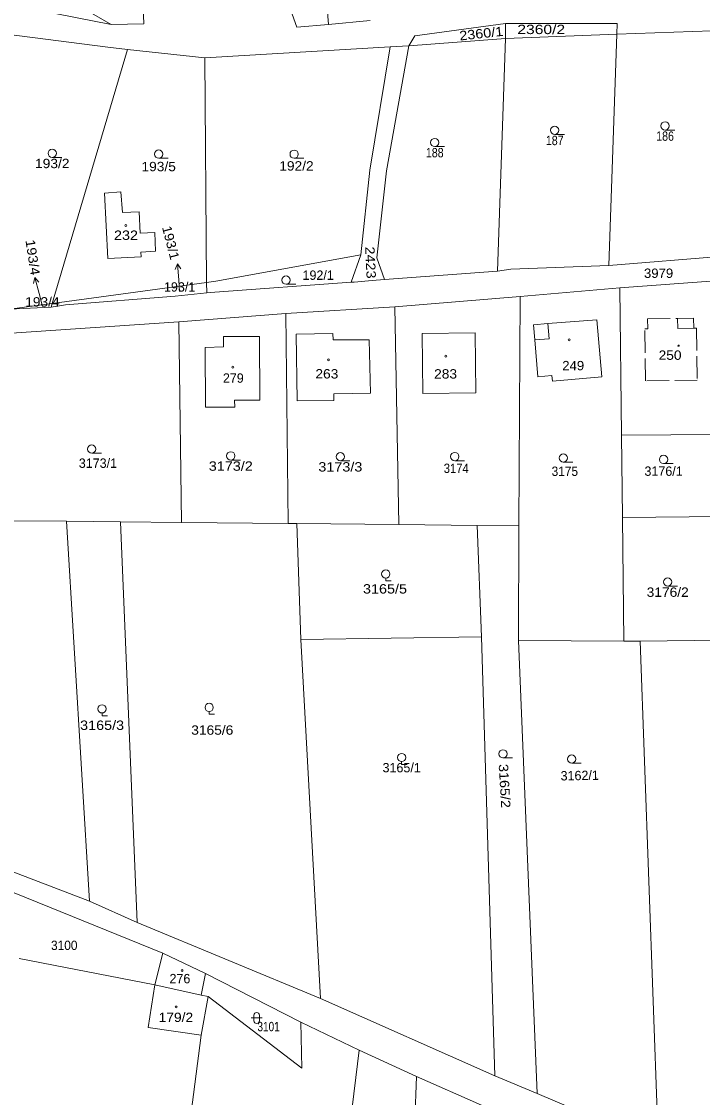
# Model space of a CAD drawing. Extents: x -590528 to -586543, y -1119609 to -1116685.
# Drawn here: x -588918.3 to -588794.5, y -1118317.2 to -1118121.8 of the extents above; entities that cross this region are included whole.
import ezdxf
from ezdxf.enums import TextEntityAlignment as Align

# ---------------------------------------------------------------- set-up
doc = ezdxf.new("R2010")
doc.units = 0
doc.header["$LTSCALE"] = 0.68
doc.linetypes.add('LONG_DASHED', pattern=[7.5, 6, -1.5])
for name, color, linetype, lineweight in [('1', 7, 'Continuous', 13), ('2', 7, 'LONG_DASHED', 13), ('3', 7, 'Continuous', 13), ('6', 7, 'Continuous', 13)]:
    doc.layers.add(name, color=color, linetype=linetype, lineweight=lineweight)

msp = doc.modelspace()

# ---------------------------------------------------------------- linework, layer by layer
at = {"layer": '1'}
for p, q in [((-588921.38, -1118118.49), (-588901.98, -1118122.35)), ((-588896.04, -1118122.23), (-588896.14, -1118119.24)), ((-588862.48, -1118122.31), (-588854.92, -1118121.59)), ((-588896.04, -1118122.23), (-588901.98, -1118122.35)), ((-588902.6, -1118126.42), (-588920.96, -1118124.06)), ((-588830.31, -1118124.87), (-588810.07, -1118124.07)), ((-588810.07, -1118124.07), (-588811.54, -1118166.12)), ((-588851.29, -1118126.41), (-588854.96, -1118148.79)), ((-588847.89, -1118126.18), (-588851.91, -1118148.91)), ((-588884.62, -1118169.19), (-588884.95, -1118128.37)), ((-588854.96, -1118148.79), (-588856.61, -1118164.19)), ((-588851.91, -1118148.91), (-588853.69, -1118164.7)), ((-588903.19, -1118152.99), (-588900.21, -1118152.75)), ((-588899.91, -1118156.48), (-588900.21, -1118152.75)), ((-588899.91, -1118156.48), (-588896.85, -1118156.35)), ((-588896.69, -1118160.23), (-588896.85, -1118156.35)), ((-588894.05, -1118160.12), (-588896.69, -1118160.23)), ((-588893.91, -1118163.53), (-588894.05, -1118160.12)), ((-588856.61, -1118164.19), (-588858.33, -1118169.16)), ((-588853.69, -1118164.7), (-588852.27, -1118168.64)), ((-588790.67, -1118164.38), (-588811.54, -1118166.12)), ((-588811.54, -1118166.12), (-588829.34, -1118166.77)), ((-588854.57, -1118168.83), (-588852.27, -1118168.64)), ((-588852.27, -1118168.64), (-588831.79, -1118167.15)), ((-588831.79, -1118167.15), (-588829.34, -1118166.77)), ((-588884.6, -1118171.06), (-588884.62, -1118169.19)), ((-588883.12, -1118170.94), (-588858.33, -1118169.16)), ((-588858.33, -1118169.16), (-588857.79, -1118169.12)), ((-588857.79, -1118169.12), (-588854.57, -1118168.83)), ((-588827.67, -1118171.72), (-588809.52, -1118170.19)), ((-588809.23, -1118196.92), (-588809.52, -1118170.19)), ((-588910.29, -1118173.25), (-588890.36, -1118171.66)), ((-588890.36, -1118171.66), (-588884.6, -1118171.06)), ((-588884.6, -1118171.06), (-588883.12, -1118170.94)), ((-588850.41, -1118173.6), (-588827.67, -1118171.72)), ((-588870.25, -1118174.81), (-588850.41, -1118173.6)), ((-588849.68, -1118213.18), (-588850.41, -1118173.6)), ((-588889.64, -1118176.31), (-588920.1, -1118178.41)), ((-588889.64, -1118176.31), (-588870.25, -1118174.81)), ((-588889.19, -1118212.78), (-588889.64, -1118176.31)), ((-588869.8, -1118212.97), (-588870.25, -1118174.81)), ((-588854.85, -1118189.3), (-588855.08, -1118179.59)), ((-588845.36, -1118189.35), (-588845.46, -1118178.46)), ((-588884.88, -1118181), (-588881.54, -1118180.86)), ((-588884.8, -1118191.86), (-588884.88, -1118181)), ((-588879.52, -1118191.82), (-588884.8, -1118191.86)), ((-588791.29, -1118196.8), (-588809.23, -1118196.92)), ((-588809.23, -1118196.92), (-588809.06, -1118211.89)), ((-588910.11, -1118212.57), (-588905.88, -1118281.56)), ((-588897.24, -1118285.43), (-588900.28, -1118212.67)), ((-588900.28, -1118212.67), (-588889.19, -1118212.78)), ((-588889.19, -1118212.78), (-588869.8, -1118212.97)), ((-588869.8, -1118212.97), (-588868.22, -1118212.99)), ((-588868.22, -1118212.99), (-588867.52, -1118234.07)), ((-588835.44, -1118213.32), (-588834.7, -1118233.55)), ((-588835.44, -1118213.32), (-588827.88, -1118213.39)), ((-588790.86, -1118211.7), (-588809.06, -1118211.89)), ((-588809.06, -1118211.89), (-588808.81, -1118234.37)), ((-588867.52, -1118234.07), (-588834.7, -1118233.55)), ((-588867.52, -1118234.07), (-588863.93, -1118299.24)), ((-588834.7, -1118233.55), (-588832.25, -1118313.27)), ((-588827.98, -1118234.2), (-588808.81, -1118234.37)), ((-588827.98, -1118234.2), (-588824.58, -1118316.52)), ((-588805.82, -1118234.34), (-588802.56, -1118325.8)), ((-588905.88, -1118281.56), (-588948.76, -1118265.18)), ((-588921.53, -1118279.24), (-588892.58, -1118291.03)), ((-588905.88, -1118281.56), (-588897.24, -1118285.43)), ((-588897.24, -1118285.43), (-588863.93, -1118299.24)), ((-588892.58, -1118291.03), (-588884.8, -1118294.68)), ((-588894, -1118296.78), (-588918.7, -1118292.01)), ((-588884.8, -1118294.68), (-588885.6, -1118298.63)), ((-588885.6, -1118298.63), (-588894, -1118296.78)), ((-588884.32, -1118298.91), (-588885.6, -1118298.63)), ((-588884.32, -1118298.91), (-588867.3, -1118311.88)), ((-588863.93, -1118299.24), (-588832.25, -1118313.27)), ((-588885.59, -1118305.94), (-588895.27, -1118304.49)), ((-588867.3, -1118311.88), (-588867.49, -1118303.56)), ((-588856.9, -1118308.63), (-588863.85, -1118365.56)), ((-588824.58, -1118316.52), (-588832.25, -1118313.27)), ((-588848.61, -1118373.89), (-588846.49, -1118313.43)), ((-588802.56, -1118325.8), (-588824.58, -1118316.52))]:
    msp.add_line(p, q, dxfattribs=at)
for points in [[(-588863.89, -1118102.64), (-588862.81, -1118117.75), (-588862.48, -1118122.31), (-588868.2, -1118122.84), (-588869.94, -1118118.08)], [(-588918.11, -1118109.25), (-588909.85, -1118117.75), (-588901.98, -1118122.35)], [(-588847.89, -1118126.18), (-588846.78, -1118124.38), (-588830.31, -1118122.15), (-588830.31, -1118124.87)], [(-588830.31, -1118122.15), (-588810.04, -1118122.15), (-588810.07, -1118124.07)], [(-588810.07, -1118124.07), (-588789.39, -1118123.38), (-588790.67, -1118164.38)], [(-588884.95, -1118128.37), (-588851.29, -1118126.41), (-588847.89, -1118126.18), (-588830.31, -1118124.87), (-588831.79, -1118167.15)], [(-588898.98, -1118126.89), (-588912.66, -1118173), (-588912.87, -1118173.7)], [(-588884.95, -1118128.37), (-588898.98, -1118126.89), (-588902.6, -1118126.42)], [(-588903.19, -1118152.99), (-588902.55, -1118164.84), (-588896.51, -1118164.53)], [(-588893.91, -1118163.53), (-588896.55, -1118163.67), (-588896.51, -1118164.53)], [(-588884.62, -1118169.19), (-588882.94, -1118168.96), (-588856.61, -1118164.19)], [(-588920.43, -1118174.06), (-588912.66, -1118173), (-588884.62, -1118169.19)], [(-588809.52, -1118170.19), (-588792.21, -1118168.92), (-588791.29, -1118196.8)], [(-588827.67, -1118171.72), (-588827.88, -1118213.39), (-588827.98, -1118234.2)], [(-588920.43, -1118174.06), (-588912.87, -1118173.7), (-588910.29, -1118173.25)], [(-588825.2, -1118176.88), (-588822.6, -1118176.67), (-588813.69, -1118175.95)], [(-588821.8, -1118187.11), (-588812.81, -1118186.35), (-588813.69, -1118175.95)], [(-588845.36, -1118189.35), (-588835.69, -1118189.21), (-588835.8, -1118178.35), (-588845.46, -1118178.46)], [(-588825.2, -1118176.88), (-588824.99, -1118179.63), (-588824.45, -1118186.32), (-588821.89, -1118186.11), (-588821.8, -1118187.11)], [(-588874.99, -1118178.99), (-588881.53, -1118178.99), (-588881.54, -1118180.86)], [(-588874.99, -1118178.99), (-588874.94, -1118190.54), (-588879.53, -1118190.57), (-588879.52, -1118191.82)], [(-588855.08, -1118179.59), (-588861.65, -1118179.61), (-588861.67, -1118178.46), (-588868.37, -1118178.55), (-588868.18, -1118190.71)], [(-588868.18, -1118190.71), (-588861.48, -1118190.61), (-588861.5, -1118189.41), (-588854.85, -1118189.3)], [(-588919.7, -1118212.47), (-588910.11, -1118212.57), (-588900.28, -1118212.67)], [(-588868.22, -1118212.99), (-588849.68, -1118213.18), (-588835.44, -1118213.32)], [(-588808.81, -1118234.37), (-588805.82, -1118234.34), (-588791.09, -1118234.19), (-588773.86, -1118234.48), (-588772.6, -1118234.5)], [(-588892.58, -1118291.03), (-588894, -1118296.78), (-588895.27, -1118304.49)], [(-588856.9, -1118308.63), (-588867.49, -1118303.56), (-588884.8, -1118294.68)], [(-588884.32, -1118298.91), (-588885.59, -1118305.94), (-588889.71, -1118337.74)], [(-588834.65, -1118318.61), (-588846.49, -1118313.43), (-588856.9, -1118308.63)]]:
    msp.add_lwpolyline(points, dxfattribs=at)
at = {"layer": '2'}
for p, q in [((-588804.46, -1118177.62), (-588804.49, -1118175.8)), ((-588799.05, -1118175.72), (-588799.02, -1118177.54)), ((-588804.46, -1118177.62), (-588805.01, -1118177.63)), ((-588799.02, -1118177.54), (-588796.11, -1118177.49))]:
    msp.add_line(p, q, dxfattribs=at)
for points in [[(-588804.49, -1118175.8), (-588799.05, -1118175.72), (-588796.14, -1118175.67)], [(-588796.14, -1118175.67), (-588796.11, -1118177.49), (-588795.61, -1118177.48)], [(-588824.99, -1118179.63), (-588822.39, -1118179.41), (-588822.6, -1118176.67)], [(-588795.61, -1118177.48), (-588795.46, -1118186.93), (-588804.85, -1118187.08), (-588805.01, -1118177.63)]]:
    msp.add_lwpolyline(points, dxfattribs=at)
at = {"layer": '3'}
for p, q in [((-588889.886, -1118165.778), (-588889.67, -1118168.77)), ((-588915.821, -1118168.286), (-588915.07, -1118171.19)), ((-588889.52, -1118170.85), (-588889.67, -1118168.77)), ((-588914.46, -1118173.56), (-588915.07, -1118171.19))]:
    msp.add_line(p, q, dxfattribs=at)
for points in [[(-588890.312, -1118166.811), (-588889.886, -1118165.778), (-588889.314, -1118166.74)], [(-588916.054, -1118169.378), (-588915.821, -1118168.286), (-588915.085, -1118169.129)]]:
    msp.add_lwpolyline(points, dxfattribs=at)
at = {"layer": '6'}
for p, q in [((-588821.37, -1118142.29), (-588819.62, -1118142.29)), ((-588801.32, -1118141.5), (-588799.57, -1118141.5)), ((-588843.17, -1118144.51), (-588841.42, -1118144.51)), ((-588912.67, -1118146.47), (-588910.92, -1118146.47)), ((-588893.33, -1118146.62), (-588891.58, -1118146.62)), ((-588868.72, -1118146.63), (-588866.97, -1118146.63)), ((-588870.19, -1118169.51), (-588868.44, -1118169.51)), ((-588905.5, -1118200.2), (-588903.75, -1118200.2)), ((-588880.23, -1118201.44), (-588878.48, -1118201.44)), ((-588860.32, -1118201.58), (-588858.57, -1118201.58)), ((-588839.53, -1118201.56), (-588837.78, -1118201.56)), ((-588819.81, -1118201.82), (-588818.06, -1118201.82)), ((-588801.59, -1118202.08), (-588799.84, -1118202.08)), ((-588800.84, -1118224.34), (-588799.09, -1118224.34)), ((-588830.77, -1118255.56), (-588829.02, -1118255.56)), ((-588818.29, -1118256.51), (-588816.54, -1118256.51)), ((-588876.53, -1118302.79), (-588874.53, -1118302.79)), ((-588876.03, -1118303.29), (-588876.03, -1118302.29)), ((-588875.03, -1118303.29), (-588875.03, -1118302.29))]:
    msp.add_line(p, q, dxfattribs=at)
for points in [[(-588852.07, -1118222.89), (-588852.07, -1118223.39), (-588851.07, -1118223.39)], [(-588903.62, -1118247.39), (-588903.62, -1118247.89), (-588902.62, -1118247.89)], [(-588884.16, -1118247.13), (-588884.16, -1118247.63), (-588883.16, -1118247.63)], [(-588849.18, -1118256.22), (-588849.18, -1118256.72), (-588848.18, -1118256.72)]]:
    msp.add_lwpolyline(points, dxfattribs=at)
for centre, radius in [((-588821.37, -1118141.54), 0.75), ((-588801.32, -1118140.75), 0.75), ((-588843.17, -1118143.76), 0.75), ((-588912.67, -1118145.72), 0.75), ((-588893.33, -1118145.87), 0.75), ((-588868.72, -1118145.88), 0.75), ((-588899.3002, -1118158.8404), 0.175), ((-588870.19, -1118168.76), 0.75), ((-588818.7602, -1118179.6004), 0.175), ((-588798.8701, -1118180.6702), 0.1172), ((-588862.5002, -1118183.2204), 0.175), ((-588841.1502, -1118182.5604), 0.175), ((-588879.8502, -1118184.5704), 0.175), ((-588905.5, -1118199.45), 0.75), ((-588880.23, -1118200.69), 0.75), ((-588860.32, -1118200.83), 0.75), ((-588839.53, -1118200.81), 0.75), ((-588819.81, -1118201.07), 0.75), ((-588801.59, -1118201.33), 0.75), ((-588852.07, -1118222.14), 0.75), ((-588800.84, -1118223.59), 0.75), ((-588903.62, -1118246.64), 0.75), ((-588884.16, -1118246.38), 0.75), ((-588830.77, -1118254.81), 0.75), ((-588849.18, -1118255.47), 0.75), ((-588818.29, -1118255.76), 0.75), ((-588889.0902, -1118294.1804), 0.175), ((-588890.1602, -1118300.7904), 0.175)]:
    msp.add_circle(centre, radius, dxfattribs=at)
for centre, start, end in [((-588875.53, -1118302.29), 0, 179.99999), ((-588875.53, -1118303.29), 179.99999, 359.99999)]:
    msp.add_arc(centre, 0.5, start, end, dxfattribs=at)

# ---------------------------------------------------------------- texts
at = {"layer": '3', "width": 1.15}
for s, rotation, p in [('2360/1', 6.188, (-588834.6291, -1118124.8101)), ('2423', 272.613, (-588855.678, -1118165.6082)), ('3165/2', 273.358, (-588831.3168, -1118260.6997))]:
    msp.add_text(s, height=1.7, rotation=rotation, dxfattribs=at).set_placement(p, align=Align.CENTER)
at = {"layer": '3'}
for s, width, p in [('2360/2', 1.25, (-588823.8205, -1118124.07)), ('187', 0.85, (-588821.3705, -1118144.24)), ('186', 0.85, (-588801.3205, -1118143.45)), ('188', 0.85, (-588843.17, -1118146.46)), ('193/2', 1.1, (-588912.6705, -1118148.42)), ('192/2', 1.1, (-588868.3, -1118148.86)), ('193/5', 1.1, (-588893.33, -1118148.98)), ('232', 1.15, (-588899.271, -1118161.45)), ('3979', 1.05, (-588802.5, -1118168.36)), ('193/4', 1.1, (-588914.461, -1118173.56)), ('250', 1.1, (-588800.41, -1118183.24)), ('249', 1.05, (-588818.0105, -1118185.14)), ('263', 1.1, (-588862.7705, -1118186.63)), ('283', 1.1, (-588841.2005, -1118186.64)), ('3173/2', 1.15, (-588880.2305, -1118203.39)), ('3173/3', 1.15, (-588860.32, -1118203.53)), ('3174', 0.9, (-588839.26, -1118203.79)), ('3175', 0.95, (-588819.53, -1118204.33)), ('3165/5', 1.15, (-588852.21, -1118225.69)), ('3176/2', 1.1, (-588800.8405, -1118226.29)), ('3165/3', 1.15, (-588903.61, -1118250.46)), ('3165/6', 1.1, (-588883.59, -1118251.34)), ('3100', 0.95, (-588910.4905, -1118290.44)), ('179/2', 1.1, (-588890.2005, -1118303.52)), ('3101', 0.8, (-588873.36, -1118305.2))]:
    msp.add_text(s, height=1.7, dxfattribs=dict(at, width=width)).set_placement(p, align=Align.CENTER)
for s, rotation, width, p in [('193/1', 284.531, 1.1, (-588891.1698, -1118165.2155)), ('193/4', 278.687, 1.15, (-588916.5568, -1118167.9912))]:
    msp.add_text(s, height=1.7, rotation=rotation, dxfattribs=dict(at, width=width)).set_placement(p, align=Align.RIGHT)
for s, p in [('192/1', (-588864.3505, -1118168.71)), ('193/1', (-588889.52, -1118170.85)), ('279', (-588879.7705, -1118187.4)), ('3173/1', (-588904.37, -1118202.86)), ('3176/1', (-588801.59, -1118204.31)), ('3165/1', (-588849.18, -1118258.17)), ('276', (-588889.4705, -1118296.49))]:
    msp.add_text(s, height=1.7, dxfattribs=at).set_placement(p, align=Align.CENTER)
msp.add_text('3162/1', height=1.7, rotation=1.031, dxfattribs=at).set_placement((-588816.8143, -1118259.5902), align=Align.CENTER)

doc.saveas('drawing.dxf')
